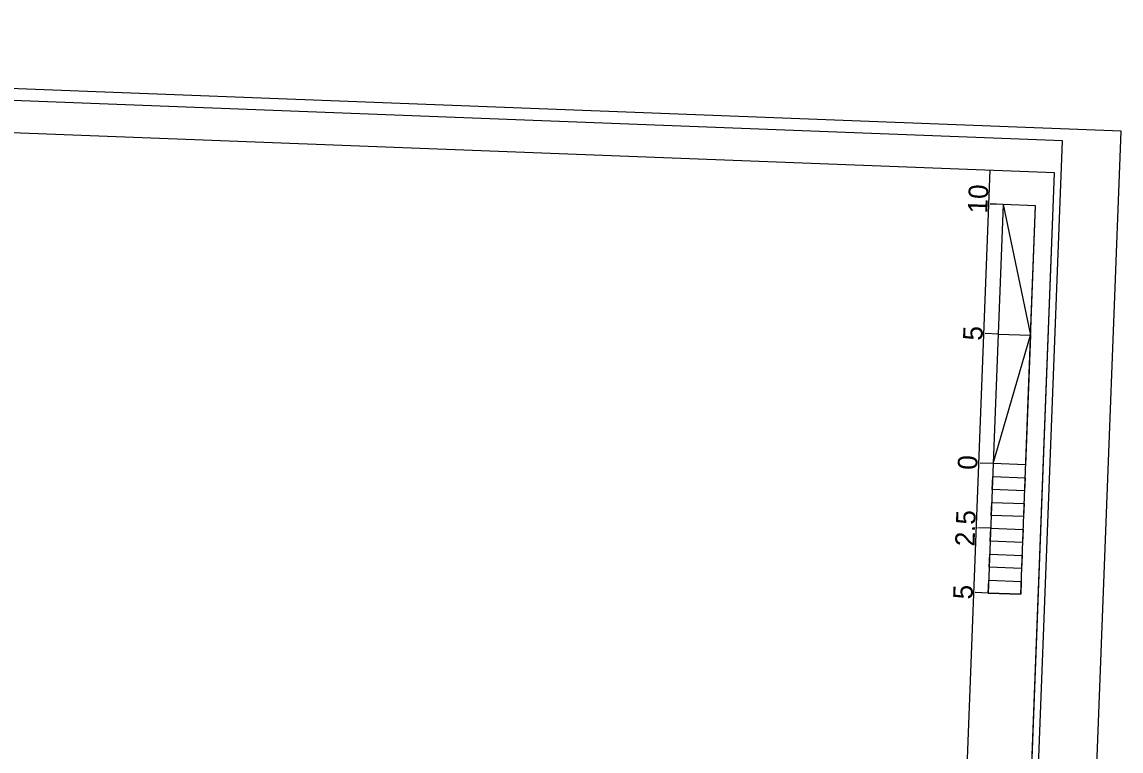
# Model space of a CAD drawing. Extents: x 2097431 to 2097897, y 685861 to 686794.
# Drawn here: x 2097727.1 to 2097896.7, y 686582.8 to 686695.3 of the extents above; entities that cross this region are included whole.
import ezdxf

# ---------------------------------------------------------------- set-up
doc = ezdxf.new("R2010")
doc.units = 0
for name, color, linetype in [('Sheet Data Field CELL', 7, 'Continuous'), ('Sheet Plan And Profile CELL', 7, 'Continuous'), ('Sheet Plot Border Inside CELL', 7, 'Continuous'), ('Sheet Plot Border Outside CELL', 7, 'Continuous'), ('Sheet Profile CELL', 7, 'Continuous'), ('Sheet Title CELL', 7, 'Continuous')]:
    doc.layers.add(name, color=color, linetype=linetype)

msp = doc.modelspace()

# ---------------------------------------------------------------- linework, layer by layer
at = {"layer": 'Sheet Data Field CELL'}
for p, q in [((2097878.51, 686667.18), (2097876.51, 686667.26)), ((2097877.74, 686647.19), (2097875.74, 686647.27)), ((2097876.59, 686617.22), (2097874.59, 686617.29)), ((2097876.2, 686607.22), (2097874.21, 686607.3))]:
    msp.add_line(p, q, dxfattribs=at)
at = {"layer": 'Sheet Plan And Profile CELL'}
msp.add_line((2097876.45, 686672.46), (2097853.46, 686072.9), dxfattribs=at)
msp.add_lwpolyline([(2097466.75, 686688.17), (2097443.76, 686088.61), (2097863.45, 686072.51), (2097886.44, 686672.07)], close=True, dxfattribs=at)
at = {"layer": 'Sheet Plot Border Inside CELL'}
msp.add_lwpolyline([(2097862.11, 686010.92), (2097887.65, 686677.03), (2097465.92, 686693.2), (2097440.38, 686027.09)], close=True, dxfattribs=at)
at = {"layer": 'Sheet Plot Border Outside CELL'}
msp.add_lwpolyline([(2097870.88, 686005.38), (2097896.7, 686678.48), (2097457.02, 686695.35), (2097431.2, 686022.24)], close=True, dxfattribs=at)
at = {"layer": 'Sheet Profile CELL'}
msp.add_line((2097863.45, 686072.51), (2097886.44, 686672.07), dxfattribs=at)
msp.add_lwpolyline([(2097466.75, 686688.17), (2097443.76, 686088.61), (2097863.45, 686072.51), (2097886.44, 686672.07)], close=True, dxfattribs=at)
at = {"layer": 'Sheet Title CELL'}
for p, q in [((2097878.51, 686667.17), (2097876.21, 686607.22)), ((2097878.51, 686667.17), (2097876.51, 686667.25)), ((2097883.51, 686666.98), (2097878.51, 686667.17)), ((2097881.21, 686607.03), (2097883.51, 686666.98)), ((2097877.74, 686647.19), (2097875.75, 686647.27)), ((2097877.74, 686647.19), (2097882.74, 686647)), ((2097876.98, 686627.2), (2097874.98, 686627.28)), ((2097876.75, 686621.21), (2097881.74, 686621.02)), ((2097876.6, 686617.21), (2097874.59, 686617.29)), ((2097876.21, 686607.22), (2097874.22, 686607.29)), ((2097874.22, 686607.29), (2097874.22, 686607.29)), ((2097876.21, 686607.22), (2097881.21, 686607.03)), ((2097876.21, 686607.22), (2097876.21, 686607.22))]:
    msp.add_line(p, q, dxfattribs=at)
for points in [[(2097878.51, 686667.17), (2097882.74, 686647), (2097883.51, 686666.98)], [(2097876.98, 686627.2), (2097882.74, 686647), (2097881.98, 686627.01)], [(2097876.82, 686623.21), (2097876.9, 686625.2), (2097881.9, 686625.01), (2097881.82, 686623.01)], [(2097876.67, 686619.21), (2097876.75, 686621.21), (2097881.74, 686621.02), (2097881.67, 686619.02)], [(2097876.52, 686615.21), (2097876.6, 686617.21), (2097881.59, 686617.02), (2097881.51, 686615.02)], [(2097876.36, 686611.22), (2097876.44, 686613.21), (2097881.44, 686613.02), (2097881.36, 686611.03)], [(2097876.21, 686607.22), (2097876.29, 686609.22), (2097881.28, 686609.02), (2097881.21, 686607.03)]]:
    msp.add_lwpolyline(points, close=True, dxfattribs=at)

# ---------------------------------------------------------------- texts
at = {"layer": 'Sheet Data Field CELL'}
for s, p in [('10', (2097876.05, 686665.76)), ('5', (2097875.3, 686646.14)), ('2.5', (2097874.08, 686614.39)), ('5', (2097873.77, 686606.21))]:
    msp.add_text(s, height=3, rotation=87.8037, dxfattribs=at).set_placement(p)
at = {"layer": 'Sheet Title CELL'}
msp.add_text('0', height=3, rotation=87.8037, dxfattribs=at).set_placement((2097874.48, 686626.2))

doc.saveas('drawing.dxf')
